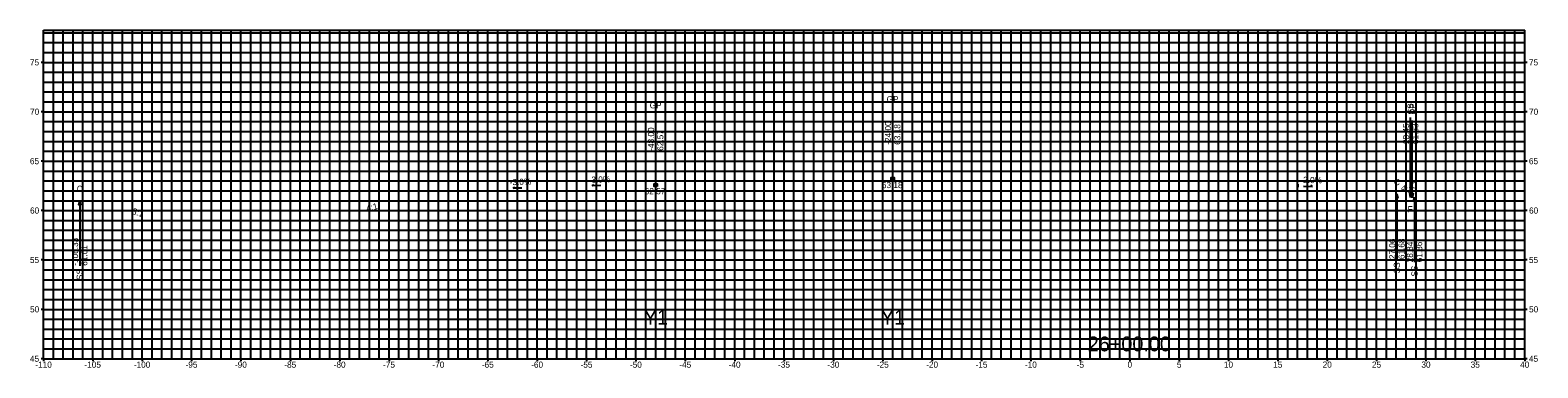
# Model space of a CAD drawing. Extents: x -111 to 41, y 44 to 78.
import ezdxf

# ---------------------------------------------------------------- set-up
doc = ezdxf.new("R2010")
doc.units = 0
for name, color, linetype in [('E_NCDOT_XS_Center_Line_Elevation_Label', 7, 'Continuous'), ('P_NCDOT_XS_Label_Grade_Point', 7, 'Continuous'), ('P_NCDOT_XS_Label_Grading_Side_Slope', 7, 'Continuous'), ('P_NCDOT_XS_Label_Slope_Superelevation', 7, 'Continuous'), ('P_NCDOT_XS_Leader_Line', 7, 'Continuous'), ('P_NCDOT_XS_Sheet_Alignment_Station_Label', 7, 'Continuous'), ('P_NCDOT_XS_Sheet_Annotation_Label', 7, 'Continuous'), ('P_NCDOT_XS_Sheet_Grid_Border', 7, 'Continuous'), ('P_NCDOT_XS_Slope_Label', 7, 'Continuous'), ('P_RDY_XS_EOT_Tick_Mark', 7, 'Continuous'), ('Prop XS Label Slope Superelevation', 7, 'Continuous'), ('Sheet_Grid_Major', 7, 'Continuous'), ('Sheet_Grid_Middle', 7, 'Continuous'), ('Sheet_Grid_Minor', 7, 'Continuous')]:
    doc.layers.add(name, color=color, linetype=linetype)

msp = doc.modelspace()

# ---------------------------------------------------------------- linework, layer by layer
at = {"layer": 'P_NCDOT_XS_Leader_Line'}
for p, q in [((-24, 63.18), (-24, 70.38)), ((-48, 62.57), (-48, 69.77)), ((28.45, 61.33), (28.45, 69.43)), ((28.6, 61.3), (28.6, 69.1)), ((27.06, 61.68), (27.06, 55.08)), ((28.84, 61.36), (28.84, 54.76)), ((-106.33, 61.01), (-106.33, 54.41))]:
    msp.add_line(p, q, dxfattribs=at)
for points in [[(-47.85, 62.42), (-48.15, 62.42), (-48.15, 62.72), (-47.85, 62.72)], [(-23.85, 63.03), (-24.15, 63.03), (-24.15, 63.33), (-23.85, 63.33)], [(27.06, 61.68), (27.15, 61.27), (26.97, 61.27)], [(28.45, 61.33), (28.36, 61.74), (28.54, 61.74)], [(28.6, 61.3), (28.52, 61.71), (28.69, 61.71)], [(28.84, 61.36), (28.93, 60.94), (28.75, 60.94)], [(-106.33, 61.01), (-106.25, 60.59), (-106.42, 60.59)]]:
    msp.add_lwpolyline(points, close=True, dxfattribs=at)
at = {"layer": 'P_NCDOT_XS_Sheet_Grid_Border'}
for p, q in [((-110, 78.26), (40, 78.26)), ((-110, 45), (-110, 78.26)), ((40, 45), (40, 78.26)), ((-110, 45), (40, 45))]:
    msp.add_line(p, q, dxfattribs=at)
at = {"layer": 'P_RDY_XS_EOT_Tick_Mark'}
for p, q in [((17.06, 62.36), (17.06, 62.67)), ((-60, 62.21), (-60, 62.52))]:
    msp.add_line(p, q, dxfattribs=at)
at = {"layer": 'Prop XS Label Slope Superelevation'}
for p, q in [((-54.45, 62.49), (-54.28, 62.62)), ((-62.45, 62.25), (-62.28, 62.38)), ((-61.55, 62.28), (-62.45, 62.25)), ((-53.55, 62.52), (-54.45, 62.49)), ((17.61, 62.47), (18.51, 62.45)), ((18.51, 62.45), (18.34, 62.58))]:
    msp.add_line(p, q, dxfattribs=at)
at = {"layer": 'Sheet_Grid_Major'}
for p, q in [((-100, 45), (-100, 78.26)), ((-90, 45), (-90, 78.26)), ((-80, 45), (-80, 78.26)), ((-70, 45), (-70, 78.26)), ((-60, 45), (-60, 78.26)), ((-50, 45), (-50, 78.26)), ((-40, 45), (-40, 78.26)), ((-30, 45), (-30, 78.26)), ((-20, 45), (-20, 78.26)), ((-10, 45), (-10, 78.26)), ((0, 45), (0, 78.26)), ((10, 45), (10, 78.26)), ((20, 45), (20, 78.26)), ((30, 45), (30, 78.26)), ((-110, 70), (40, 70)), ((-110, 60), (40, 60)), ((-110, 50), (40, 50))]:
    msp.add_line(p, q, dxfattribs=at)
at = {"layer": 'Sheet_Grid_Middle'}
for p, q in [((-105, 45), (-105, 78.26)), ((-100, 45), (-100, 78.26)), ((-95, 45), (-95, 78.26)), ((-90, 45), (-90, 78.26)), ((-85, 45), (-85, 78.26)), ((-80, 45), (-80, 78.26)), ((-75, 45), (-75, 78.26)), ((-70, 45), (-70, 78.26)), ((-65, 45), (-65, 78.26)), ((-60, 45), (-60, 78.26)), ((-55, 45), (-55, 78.26)), ((-50, 45), (-50, 78.26)), ((-45, 45), (-45, 78.26)), ((-40, 45), (-40, 78.26)), ((-35, 45), (-35, 78.26)), ((-30, 45), (-30, 78.26)), ((-25, 45), (-25, 78.26)), ((-20, 45), (-20, 78.26)), ((-15, 45), (-15, 78.26)), ((-10, 45), (-10, 78.26)), ((-5, 45), (-5, 78.26)), ((0, 45), (0, 78.26)), ((5, 45), (5, 78.26)), ((10, 45), (10, 78.26)), ((15, 45), (15, 78.26)), ((20, 45), (20, 78.26)), ((25, 45), (25, 78.26)), ((30, 45), (30, 78.26)), ((35, 45), (35, 78.26)), ((-110, 75), (-110.24, 75)), ((-110, 75), (40, 75)), ((40.24, 75), (40, 75)), ((-110, 70), (-110.24, 70)), ((-110, 70), (40, 70)), ((40.24, 70), (40, 70)), ((-110, 65), (-110.24, 65)), ((-110, 65), (40, 65)), ((40.24, 65), (40, 65)), ((-110, 60), (-110.24, 60)), ((-110, 60), (40, 60)), ((40.24, 60), (40, 60)), ((-110, 55), (-110.24, 55)), ((-110, 55), (40, 55)), ((40.24, 55), (40, 55)), ((-110, 50), (-110.24, 50)), ((-110, 50), (40, 50)), ((40.24, 50), (40, 50)), ((-110, 45), (-110.24, 45)), ((-110, 45), (-110, 44.76)), ((-105, 45), (-105, 44.76)), ((-100, 45), (-100, 44.76)), ((-95, 45), (-95, 44.76)), ((-90, 45), (-90, 44.76)), ((-85, 45), (-85, 44.76)), ((-80, 45), (-80, 44.76)), ((-75, 45), (-75, 44.76)), ((-70, 45), (-70, 44.76)), ((-65, 45), (-65, 44.76)), ((-60, 45), (-60, 44.76)), ((-55, 45), (-55, 44.76)), ((-50, 45), (-50, 44.76)), ((-45, 45), (-45, 44.76)), ((-40, 45), (-40, 44.76)), ((-35, 45), (-35, 44.76)), ((-30, 45), (-30, 44.76)), ((-25, 45), (-25, 44.76)), ((-20, 45), (-20, 44.76)), ((-15, 45), (-15, 44.76)), ((-10, 45), (-10, 44.76)), ((-5, 45), (-5, 44.76)), ((0, 45), (0, 44.76)), ((5, 45), (5, 44.76)), ((10, 45), (10, 44.76)), ((15, 45), (15, 44.76)), ((20, 45), (20, 44.76)), ((25, 45), (25, 44.76)), ((30, 45), (30, 44.76)), ((35, 45), (35, 44.76)), ((40, 45), (40, 44.76)), ((40.24, 45), (40, 45))]:
    msp.add_line(p, q, dxfattribs=at)
at = {"layer": 'Sheet_Grid_Minor'}
for p, q in [((-110, 78), (40, 78)), ((-109, 45), (-109, 78.26)), ((-108, 45), (-108, 78.26)), ((-107, 45), (-107, 78.26)), ((-106, 45), (-106, 78.26)), ((-104, 45), (-104, 78.26)), ((-103, 45), (-103, 78.26)), ((-102, 45), (-102, 78.26)), ((-101, 45), (-101, 78.26)), ((-99, 45), (-99, 78.26)), ((-98, 45), (-98, 78.26)), ((-97, 45), (-97, 78.26)), ((-96, 45), (-96, 78.26)), ((-94, 45), (-94, 78.26)), ((-93, 45), (-93, 78.26)), ((-92, 45), (-92, 78.26)), ((-91, 45), (-91, 78.26)), ((-89, 45), (-89, 78.26)), ((-88, 45), (-88, 78.26)), ((-87, 45), (-87, 78.26)), ((-86, 45), (-86, 78.26)), ((-84, 45), (-84, 78.26)), ((-83, 45), (-83, 78.26)), ((-82, 45), (-82, 78.26)), ((-81, 45), (-81, 78.26)), ((-79, 45), (-79, 78.26)), ((-78, 45), (-78, 78.26)), ((-77, 45), (-77, 78.26)), ((-76, 45), (-76, 78.26)), ((-74, 45), (-74, 78.26)), ((-73, 45), (-73, 78.26)), ((-72, 45), (-72, 78.26)), ((-71, 45), (-71, 78.26)), ((-69, 45), (-69, 78.26)), ((-68, 45), (-68, 78.26)), ((-67, 45), (-67, 78.26)), ((-66, 45), (-66, 78.26)), ((-64, 45), (-64, 78.26)), ((-63, 45), (-63, 78.26)), ((-62, 45), (-62, 78.26)), ((-61, 45), (-61, 78.26)), ((-59, 45), (-59, 78.26)), ((-58, 45), (-58, 78.26)), ((-57, 45), (-57, 78.26)), ((-56, 45), (-56, 78.26)), ((-54, 45), (-54, 78.26)), ((-53, 45), (-53, 78.26)), ((-52, 45), (-52, 78.26)), ((-51, 45), (-51, 78.26)), ((-49, 45), (-49, 78.26)), ((-48, 45), (-48, 78.26)), ((-47, 45), (-47, 78.26)), ((-46, 45), (-46, 78.26)), ((-44, 45), (-44, 78.26)), ((-43, 45), (-43, 78.26)), ((-42, 45), (-42, 78.26)), ((-41, 45), (-41, 78.26)), ((-39, 45), (-39, 78.26)), ((-38, 45), (-38, 78.26)), ((-37, 45), (-37, 78.26)), ((-36, 45), (-36, 78.26)), ((-34, 45), (-34, 78.26)), ((-33, 45), (-33, 78.26)), ((-32, 45), (-32, 78.26)), ((-31, 45), (-31, 78.26)), ((-29, 45), (-29, 78.26)), ((-28, 45), (-28, 78.26)), ((-27, 45), (-27, 78.26)), ((-26, 45), (-26, 78.26)), ((-24, 45), (-24, 78.26)), ((-23, 45), (-23, 78.26)), ((-22, 45), (-22, 78.26)), ((-21, 45), (-21, 78.26)), ((-19, 45), (-19, 78.26)), ((-18, 45), (-18, 78.26)), ((-17, 45), (-17, 78.26)), ((-16, 45), (-16, 78.26)), ((-14, 45), (-14, 78.26)), ((-13, 45), (-13, 78.26)), ((-12, 45), (-12, 78.26)), ((-11, 45), (-11, 78.26)), ((-9, 45), (-9, 78.26)), ((-8, 45), (-8, 78.26)), ((-7, 45), (-7, 78.26)), ((-6, 45), (-6, 78.26)), ((-4, 45), (-4, 78.26)), ((-3, 45), (-3, 78.26)), ((-2, 45), (-2, 78.26)), ((-1, 45), (-1, 78.26)), ((1, 45), (1, 78.26)), ((2, 45), (2, 78.26)), ((3, 45), (3, 78.26)), ((4, 45), (4, 78.26)), ((6, 45), (6, 78.26)), ((7, 45), (7, 78.26)), ((8, 45), (8, 78.26)), ((9, 45), (9, 78.26)), ((11, 45), (11, 78.26)), ((12, 45), (12, 78.26)), ((13, 45), (13, 78.26)), ((14, 45), (14, 78.26)), ((16, 45), (16, 78.26)), ((17, 45), (17, 78.26)), ((18, 45), (18, 78.26)), ((19, 45), (19, 78.26)), ((21, 45), (21, 78.26)), ((22, 45), (22, 78.26)), ((23, 45), (23, 78.26)), ((24, 45), (24, 78.26)), ((26, 45), (26, 78.26)), ((27, 45), (27, 78.26)), ((28, 45), (28, 78.26)), ((29, 45), (29, 78.26)), ((31, 45), (31, 78.26)), ((32, 45), (32, 78.26)), ((33, 45), (33, 78.26)), ((34, 45), (34, 78.26)), ((36, 45), (36, 78.26)), ((37, 45), (37, 78.26)), ((38, 45), (38, 78.26)), ((39, 45), (39, 78.26)), ((-110, 77), (40, 77)), ((-110, 76), (40, 76)), ((-110, 74), (40, 74)), ((-110, 73), (40, 73)), ((-110, 72), (40, 72)), ((-110, 71), (40, 71)), ((-110, 69), (40, 69)), ((-110, 68), (40, 68)), ((-110, 67), (40, 67)), ((-110, 66), (40, 66)), ((-110, 64), (40, 64)), ((-110, 63), (40, 63)), ((-110, 62), (40, 62)), ((-110, 61), (40, 61)), ((-110, 59), (40, 59)), ((-110, 58), (40, 58)), ((-110, 57), (40, 57)), ((-110, 56), (40, 56)), ((-110, 54), (40, 54)), ((-110, 53), (40, 53)), ((-110, 52), (40, 52)), ((-110, 51), (40, 51)), ((-110, 49), (40, 49)), ((-110, 48), (40, 48)), ((-110, 47), (40, 47)), ((-110, 46), (40, 46))]:
    msp.add_line(p, q, dxfattribs=at)

# ---------------------------------------------------------------- texts
at = {"layer": 'E_NCDOT_XS_Center_Line_Elevation_Label'}
for s, p in [('63.18', (-25.09, 62.27)), ('62.57', (-49.11, 61.65))]:
    msp.add_text(s, height=0.624, dxfattribs=at).set_placement(p)
at = {"layer": 'P_NCDOT_XS_Label_Grade_Point'}
for p in [(-48.61, 70.34), (-24.61, 70.96)]:
    msp.add_text('GP', height=0.624, dxfattribs=at).set_placement(p)
for s, p in [('-24.00', (-24.16, 66.66)), ('63.18', (-23.22, 66.66)), ('-48.00', (-48.16, 66.05)), ('62.57', (-47.22, 66.05))]:
    msp.add_text(s, height=0.624, rotation=90, dxfattribs=at).set_placement(p)
at = {"layer": 'P_NCDOT_XS_Label_Grading_Side_Slope'}
for s, p in [('SS', (28.76, 69.73)), ('DP', (28.92, 69.7)), ('28.45', (28.3, 66.73)), ('61.33', (29.23, 66.73)), ('-106.33', (-106.49, 54.41)), ('27.06', (26.9, 55.08)), ('61.68', (27.84, 55.08)), ('28.84', (28.68, 54.76)), ('61.36', (29.62, 54.76)), ('61.01', (-105.55, 54.41)), ('SS', (-106.02, 52.97)), ('SS', (27.37, 53.64)), ('SS', (29.15, 53.32))]:
    msp.add_text(s, height=0.624, rotation=90, dxfattribs=at).set_placement(p)
for s, p in [('C', (26.76, 62.57)), ('C', (28.54, 62.24)), ('C', (-106.63, 61.89)), ('F', (28.15, 59.82))]:
    msp.add_text(s, height=0.624, dxfattribs=at).set_placement(p)
at = {"layer": 'P_NCDOT_XS_Label_Slope_Superelevation'}
msp.add_text('-3.0%', height=0.624, rotation=1.7184, dxfattribs=at).set_placement((-54.78, 62.8))
at = {"layer": 'P_NCDOT_XS_Sheet_Alignment_Station_Label'}
for s, p in [('Y1', (-49.2, 48.45)), ('Y1', (-25.2, 48.45)), ('26+00.00', (-4.25, 45.75))]:
    msp.add_text(s, height=1.5, dxfattribs=at).set_placement(p)
at = {"layer": 'P_NCDOT_XS_Sheet_Annotation_Label'}
for s, p in [('75', (-111.37, 74.69)), ('75', (40.43, 74.69)), ('70', (-111.36, 69.69)), ('70', (40.44, 69.69)), ('65', (-111.37, 64.69)), ('65', (40.43, 64.69)), ('60', (-111.36, 59.69)), ('60', (40.44, 59.69)), ('55', (-111.37, 54.69)), ('55', (40.43, 54.69)), ('50', (-111.36, 49.69)), ('50', (40.44, 49.69)), ('45', (-111.37, 44.69)), ('-110', (-110.82, 44.09)), ('-105', (-105.85, 44.09)), ('-100', (-100.85, 44.09)), ('-95', (-95.61, 44.09)), ('-90', (-90.61, 44.09)), ('-85', (-85.61, 44.09)), ('-80', (-80.61, 44.09)), ('-75', (-75.61, 44.09)), ('-70', (-70.61, 44.09)), ('-65', (-65.61, 44.09)), ('-60', (-60.61, 44.09)), ('-55', (-55.61, 44.09)), ('-50', (-50.61, 44.09)), ('-45', (-45.61, 44.09)), ('-40', (-40.61, 44.09)), ('-35', (-35.61, 44.09)), ('-30', (-30.61, 44.09)), ('-25', (-25.61, 44.09)), ('-20', (-20.61, 44.09)), ('-15', (-15.61, 44.09)), ('-10', (-10.61, 44.09)), ('-5', (-5.37, 44.09)), ('0', (-0.22, 44.09)), ('5', (4.78, 44.09)), ('10', (9.54, 44.09)), ('15', (14.53, 44.09)), ('20', (19.54, 44.09)), ('25', (24.53, 44.09)), ('30', (29.54, 44.09)), ('35', (34.53, 44.09)), ('40', (39.54, 44.09)), ('45', (40.43, 44.69))]:
    msp.add_text(s, height=0.624, dxfattribs=at).set_placement(p)
at = {"layer": 'P_NCDOT_XS_Slope_Label'}
for s, rotation, p in [('-3.0%', 1.7184, (-62.78, 62.56)), ('-2.0%', 358.8542, (17.28, 62.8)), ('4:1', 345.9638, (27.41, 62.02)), ('3:1', 341.5668, (-101.08, 59.68)), ('4:1', 14.0362, (-77.23, 59.89))]:
    msp.add_text(s, height=0.624, rotation=rotation, dxfattribs=at).set_placement(p)

doc.saveas('drawing.dxf')
